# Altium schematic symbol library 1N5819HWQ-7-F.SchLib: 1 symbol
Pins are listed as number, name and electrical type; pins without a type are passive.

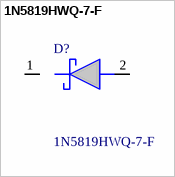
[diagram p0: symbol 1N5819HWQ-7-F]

## 1N5819HWQ-7-F
designator D?
Schottky Diode 40 V 1A Surface Mount SOD-123; Manufacturer_Name: Diodes Incorporated; Geometry.Height: 1.45mm
footprint SOD3716X145N
pins: 1 K, 2 A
